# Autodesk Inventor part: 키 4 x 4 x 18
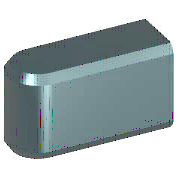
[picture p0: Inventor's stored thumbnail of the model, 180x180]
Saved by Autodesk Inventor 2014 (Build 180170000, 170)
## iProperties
IsCustomPart: 1
Created: 2012-02
Part Number: 키 4 x 4 x 18
Material: 강철, 연강
Description: 키 및 해당 키홈
Document SubType Name: Modeling
Standard: KS B 1311
Designer: mduedu
Standards Organization: KS
Language: ko-KR
Size Designation: 4 x 4 x 18
Categories: <MemberInstance><Categories><Category DisplayName="샤프트 부품" InternalName="7f7aeb1f-a693-4053-b835-cee3144e0d98" Mnemonic="SHFT"><Category DisplayName="키" Interna
Density: 1 g/cm^3
Appearance: 파란색 - 벽 페인트 - 광택
Author: mduedu
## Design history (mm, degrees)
sketch "스케치1"
  geometry: L1 (2, 2)-(18, 2); L2 (18, 2)-(18, -2); L3 (18, -2)-(2, -2); L4 (0, 7)-(0, -7) reference; L5 (-5, 0)-(30, 0) reference; A1 r 2 centre (2, 0) between (2, 2) and (2, -2)
  constraints: 6 end point, 3 tangent, 2 point on circle, 1 centre point, 1 horizontal, 1 parallel, 1 perpendicular, 1 point on line
  dimensions: "d0" = 2 radius of A1 (= 0.5 x PB); "d7" = 18 distance between parallel lines of L2 L4 (= NLG)
workplane "Work Plane1"
workplane "Work Plane2"
extrude "본체1" new body sketch "스케치1" taper "d3" = 0 deg; stored distance "d4" = 10
workaxis "Work Axis1"
workplane "Work Plane4"
body "Solid1"
chamfer "모따기1" distance "d8" = 0.25 (= PHH); stored, may be unused: second distance "d9" = 0.25 (= PHH), angle "d13" = 45 deg
other parameters: "d1" = -2.5 (= -PNT), "d2" = 1.5 (= PH - PNT), "NLG" = 18 [user parameter; used in 2 equation terms], "PB" = 4 [user parameter; used in 1 equation term], "PNT" = 2.5 [user parameter; used in 2 equation terms], "PH" = 4 [user parameter; used in 1 equation term], "PHH" = 0.25 [user parameter; used in 2 equation terms], "d10" = 0, "d16" = 0, "d17" = 0, "d18" = 0, "RR" = 0.08 [user parameter], "WDMAX" = 12 [user parameter], "PLB1" = 18 (= NLG) [user parameter], "PUEB" = 1.8 [user parameter]
